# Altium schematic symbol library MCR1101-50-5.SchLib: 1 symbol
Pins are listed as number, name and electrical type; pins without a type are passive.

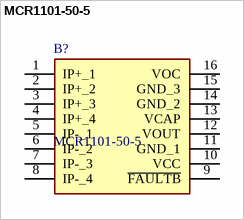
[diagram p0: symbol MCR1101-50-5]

## MCR1101-50-5
designator B?
Board Mount Current Sensors High Accuracy 50A Current Sensor, 5V, Ratiometric, 1.5MHz 3dB BW, OCP, Galvanic Isolation. UL/IEC/EN60950-1 and UL1577 certified. SOIC-16; Manufacturer_Name: ACEINNA; Geometry.Height: 2.64mm
footprint MCR1101505
pins: 1 IP+_1, 2 IP+_2, 3 IP+_3, 4 IP+_4, 5 IP-_1, 6 IP-_2, 7 IP-_3, 8 IP-_4, 9 ~{FAULTB}, 10 VCC, 11 GND_1, 12 VOUT, 13 VCAP, 14 GND_2, 15 GND_3, 16 VOC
